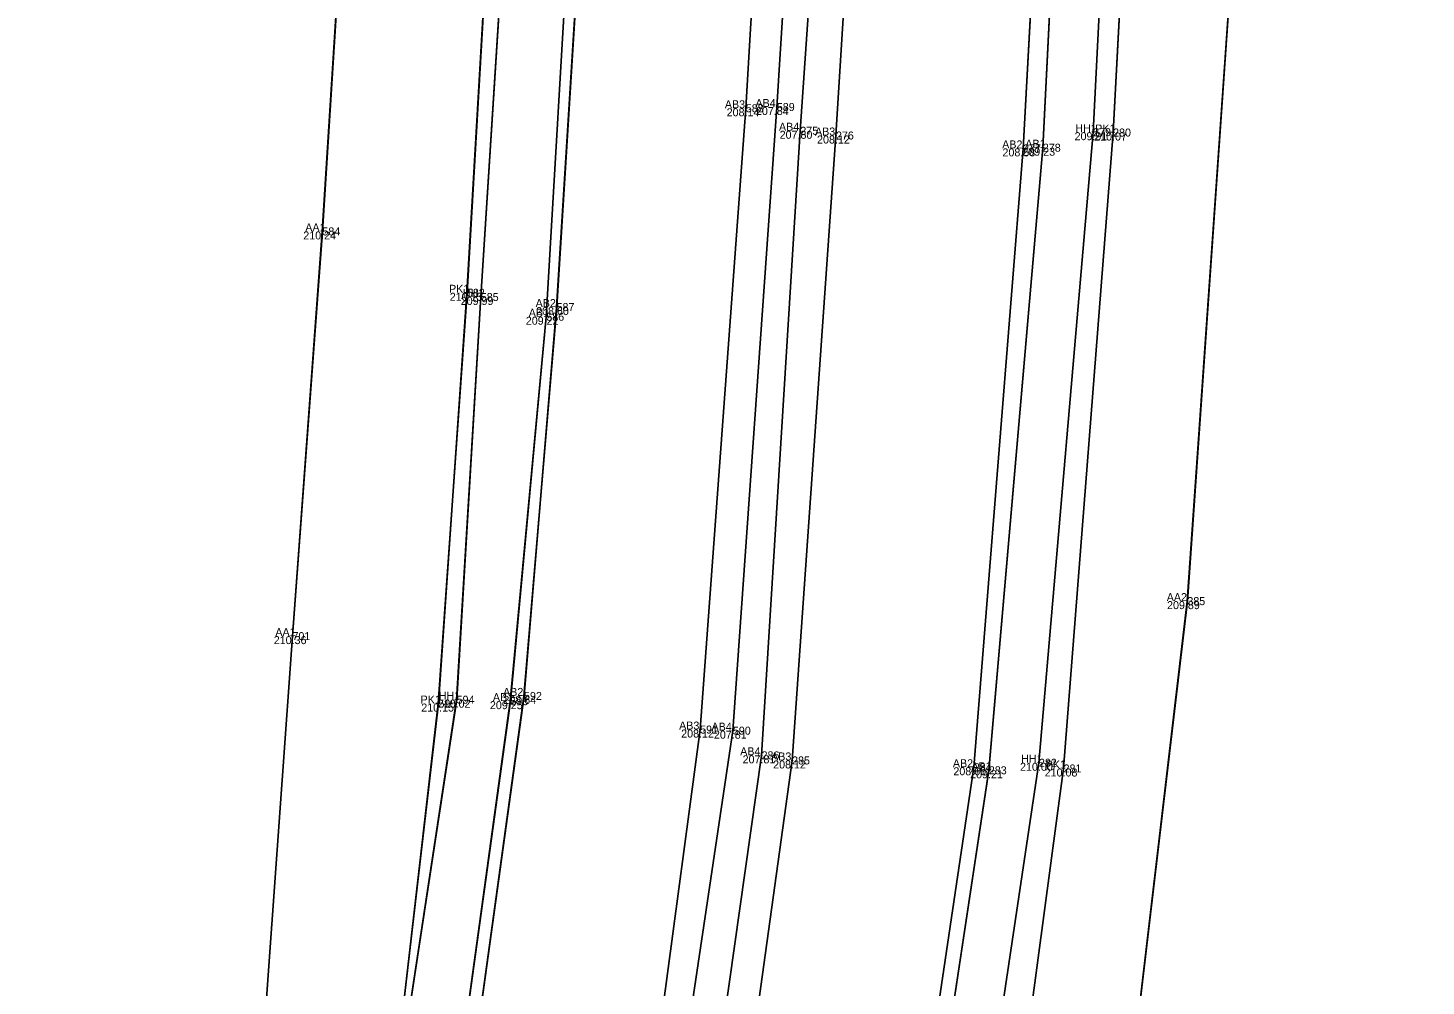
# Model space of a CAD drawing. Extents: x -263091 to -262565, y -1238731 to -1237092.
# Drawn here: x -262851.71 to -262816.76, y -1238047.41 to -1238023.45 of the extents above; entities that cross this region are included whole.
import ezdxf

# ---------------------------------------------------------------- set-up
doc = ezdxf.new("R2010")
doc.units = 0
for name, color, linetype in [('01_Hrana_betónu', 7, 'Continuous'), ('02_Oplotenie', 7, 'Continuous'), ('03_Asfalt', 7, 'Continuous'), ('05_Hrana_terénu', 7, 'Continuous'), ('09_Múrik', 7, 'Continuous'), ('Groma (21)', 7, 'Continuous'), ('Groma (22)', 7, 'Continuous'), ('Groma (23)', 7, 'Continuous'), ('Groma (24)', 7, 'Continuous'), ('U003_Asfalt', 7, 'Continuous'), ('U003_Betónové_múriky', 7, 'Continuous'), ('U003_Betónové_panely', 7, 'Continuous'), ('U003_Zeleň_mimo', 7, 'Continuous'), ('U003_Zeleň_vnútro', 7, 'Continuous'), ('U003_Zeleň_zatrávňovač', 7, 'Continuous'), ('U005_Betóny_prídavné', 7, 'Continuous')]:
    doc.layers.add(name, color=color, linetype=linetype)

msp = doc.modelspace()

# ---------------------------------------------------------------- linework, layer by layer
at = {"layer": '01_Hrana_betónu'}
for points in [[(-262903.088, -1238238.797), (-262890.817, -1238204.479), (-262885.468, -1238189.492), (-262878.003, -1238168.56), (-262870.455, -1238147.513), (-262864.947, -1238132.168), (-262859.037, -1238116.651), (-262848.977, -1238095.826), (-262842.353, -1238078.361), (-262839.446, -1238067.823), (-262836.783, -1238055.069), (-262834.905, -1238040.999), (-262833.763, -1238025.462), (-262832.297, -1238000.555), (-262831.13, -1237981.111), (-262829.791, -1237958.391), (-262828.651, -1237937.03), (-262828.571, -1237935.876)], [(-262827.762, -1237935.927), (-262827.853, -1237937.062), (-262829.049, -1237958.415), (-262830.305, -1237981.211), (-262831.433, -1238000.629), (-262832.987, -1238025.43), (-262834.086, -1238041.027), (-262836.169, -1238055.023), (-262838.684, -1238068.024), (-262841.681, -1238078.569), (-262848.285, -1238096.308), (-262858.162, -1238116.913), (-262863.876, -1238132.122), (-262869.919, -1238147.692), (-262877.244, -1238168.638), (-262884.69, -1238189.67), (-262901.991, -1238238.762)], [(-262827.034, -1237935.973), (-262827.072, -1237937.036), (-262828.491, -1237960.168), (-262829.643, -1237980.454), (-262830.754, -1238002.123), (-262832.4, -1238026.024), (-262833.369, -1238041.644), (-262835.263, -1238055.011), (-262838.048, -1238068.261), (-262841.826, -1238081.232), (-262846.645, -1238094.136), (-262857.777, -1238117.273), (-262863.292, -1238131.948), (-262884.082, -1238190.299), (-262901.352, -1238238.742)], [(-262900.376, -1238238.711), (-262890.192, -1238209.46), (-262883.463, -1238190.564), (-262868.512, -1238148.877), (-262862.514, -1238132.276), (-262857.014, -1238117.706), (-262845.846, -1238094.561), (-262841.058, -1238081.49), (-262837.218, -1238068.474), (-262834.492, -1238055.416), (-262832.606, -1238041.772), (-262831.509, -1238026.143), (-262830.024, -1238002.24), (-262828.826, -1237980.518), (-262827.576, -1237960.277), (-262826.117, -1237937.218), (-262826.079, -1237936.033)]]:
    msp.add_lwpolyline(points, dxfattribs=at)
at = {"layer": '02_Oplotenie'}
for points in [[(-262912.451, -1238238.295), (-262908.254, -1238226.663), (-262901.526, -1238207.942), (-262898.552, -1238199.602), (-262894.22, -1238186.327), (-262886.794, -1238165.648), (-262879.297, -1238144.201), (-262873.976, -1238128.814), (-262867.141, -1238113.572), (-262855.316, -1238089.931), (-262850.675, -1238078.807), (-262846.261, -1238065.654), (-262843.56, -1238054.226), (-262842.344, -1238048.099), (-262841.445, -1238040.349), (-262840.733, -1238030.077), (-262839.013, -1238000.384), (-262838.353, -1237989.712), (-262835.178, -1237935.879)], [(-262819.762, -1237938.034), (-262820.788, -1237960.675), (-262821.837, -1237980.919), (-262823.308, -1238002.106), (-262824.582, -1238026.068), (-262825.82, -1238041.973), (-262827.772, -1238056.552), (-262830.57, -1238069.546), (-262834.589, -1238083.855), (-262839.328, -1238095.835), (-262848.782, -1238120.942), (-262853.684, -1238135.175), (-262859.896, -1238152.781), (-262867.698, -1238174.329), (-262874.833, -1238193.487), (-262881.88, -1238212.036), (-262887.174, -1238225.693), (-262888.829, -1238230.138)]]:
    msp.add_lwpolyline(points, dxfattribs=at)
at = {"layer": '03_Asfalt'}
for points in [[(-262912.678, -1238239.103), (-262913.356, -1238239.285), (-262915.717, -1238239.279), (-262916.328, -1238238.784), (-262916.575, -1238236.319), (-262915.768, -1238233.661), (-262912.404, -1238225.097), (-262904.805, -1238205.606), (-262896.687, -1238184.948), (-262888.478, -1238163.929), (-262880.124, -1238142.63), (-262874.65, -1238128.675), (-262868.549, -1238113.075), (-262858.861, -1238088.481), (-262853.132, -1238074.038), (-262850.084, -1238066.288), (-262845.869, -1238049.471), (-262845.094, -1238038.662), (-262844.346, -1238028.542), (-262842.599, -1238000.955), (-262841.603, -1237985.168), (-262838.824, -1237943.888), (-262838.24, -1237934.633), (-262838.283, -1237933.488)], [(-262816.76, -1237934.791), (-262817.067, -1237940.584), (-262818.198, -1237960.603), (-262819.351, -1237980.318), (-262820.259, -1237997.242), (-262821.106, -1238014.516), (-262822.726, -1238037.787), (-262824.929, -1238056.475), (-262826.695, -1238065.295), (-262832.135, -1238081.046), (-262834.142, -1238085.994), (-262836.111, -1238090.171)]]:
    msp.add_lwpolyline(points, dxfattribs=at)
at = {"layer": '05_Hrana_terénu'}
for points in [[(-262835.062, -1237935.275), (-262834.86, -1237936.333), (-262838.087, -1237989.633), (-262838.484, -1238000.332), (-262840.387, -1238030.181), (-262840.991, -1238040.253), (-262843.126, -1238054.282), (-262845.675, -1238066.436), (-262850.413, -1238079.623), (-262854.798, -1238090.209), (-262863.856, -1238108.78), (-262866.643, -1238114.502), (-262872.333, -1238129.41), (-262877.981, -1238144.625), (-262885.616, -1238166.033), (-262893.121, -1238186.676), (-262898.244, -1238201.149), (-262900.554, -1238208.001), (-262907.375, -1238226.781), (-262911.85, -1238238.364), (-262912.678, -1238239.103)], [(-262849.564, -1238120.544), (-262839.894, -1238095.583), (-262835.301, -1238083.403), (-262831.402, -1238069.334), (-262828.632, -1238056.516), (-262826.436, -1238041.83), (-262825.08, -1238026.06), (-262823.863, -1238001.967), (-262822.633, -1237980.847), (-262821.298, -1237960.54), (-262820.334, -1237939.047), (-262819.871, -1237937.657)]]:
    msp.add_lwpolyline(points, dxfattribs=at)
at = {"layer": '09_Múrik'}
for points in [[(-262845.277, -1238070.627), (-262844.218, -1238066.744), (-262841.577, -1238054.272), (-262839.647, -1238040.289), (-262838.75, -1238030.675), (-262836.979, -1238000.411), (-262836.237, -1237989.843), (-262834.391, -1237956.949), (-262833.055, -1237935.594)], [(-262844.833, -1238070.767), (-262843.906, -1238066.814), (-262841.249, -1238054.245), (-262839.306, -1238040.158), (-262838.493, -1238030.433), (-262836.614, -1238000.277), (-262836.049, -1237989.856), (-262833.996, -1237956.678), (-262832.67, -1237935.618)], [(-262840.924, -1238094.827), (-262836.941, -1238083.068), (-262832.969, -1238069.042), (-262830.214, -1238056.416), (-262828.063, -1238041.942), (-262826.83, -1238026.465), (-262825.494, -1238001.855), (-262824.316, -1237980.84), (-262823.031, -1237960.337), (-262821.719, -1237936.336)], [(-262840.6, -1238094.732), (-262836.43, -1238082.967), (-262832.633, -1238069.1), (-262829.86, -1238056.421), (-262827.688, -1238042.018), (-262826.338, -1238026.448), (-262825.108, -1238001.872), (-262823.89, -1237980.741), (-262822.602, -1237960.47), (-262821.253, -1237936.39)]]:
    msp.add_lwpolyline(points, dxfattribs=at)
at = {"layer": 'Groma (21)'}
for centre in [(-262833.763, -1238025.462), (-262832.987, -1238025.43), (-262832.4, -1238026.024), (-262831.509, -1238026.143), (-262825.08, -1238026.06), (-262824.582, -1238026.068), (-262826.83, -1238026.465), (-262826.338, -1238026.448), (-262844.346, -1238028.542), (-262840.733, -1238030.077), (-262840.387, -1238030.181), (-262838.493, -1238030.433), (-262838.75, -1238030.675), (-262822.726, -1238037.787), (-262845.094, -1238038.662), (-262839.306, -1238040.158), (-262841.445, -1238040.349), (-262840.991, -1238040.253), (-262839.647, -1238040.289), (-262834.905, -1238040.999), (-262834.086, -1238041.027), (-262833.369, -1238041.644), (-262832.606, -1238041.772), (-262828.063, -1238041.942), (-262826.436, -1238041.83), (-262827.688, -1238042.018), (-262825.82, -1238041.973)]:
    msp.add_circle(centre, 0.01, dxfattribs=at)
at = {"layer": 'U003_Asfalt'}
for points in [[(-262836.86, -1238089.78), (-262834.59, -1238083.86), (-262830.57, -1238069.55), (-262827.77, -1238056.55), (-262825.82, -1238041.97), (-262824.58, -1238026.07), (-262823.31, -1238002.11), (-262821.84, -1237980.92), (-262820.79, -1237960.68), (-262819.76, -1237938.03), (-262819.87, -1237937.66), (-262818.51, -1237937.77), (-262818.3, -1237934.7)], [(-262816.76, -1237934.79), (-262817.07, -1237940.58), (-262818.2, -1237960.6), (-262819.35, -1237980.32), (-262820.26, -1237997.24), (-262821.11, -1238014.52), (-262822.73, -1238037.79), (-262824.93, -1238056.48), (-262826.7, -1238065.3), (-262832.14, -1238081.05), (-262834.14, -1238085.99), (-262836.11, -1238090.17), (-262836.86, -1238089.78)], [(-262821.11, -1238014.52), (-262822.73, -1238037.79), (-262824.93, -1238056.48), (-262826.7, -1238065.3), (-262832.14, -1238081.05), (-262834.14, -1238085.99), (-262836.11, -1238090.17), (-262836.86, -1238089.78), (-262834.59, -1238083.86), (-262830.57, -1238069.55), (-262827.77, -1238056.55), (-262825.82, -1238041.97), (-262824.58, -1238026.07), (-262823.31, -1238002.11)]]:
    msp.add_lwpolyline(points, dxfattribs=at)
at = {"layer": 'U003_Betónové_múriky'}
for points in [[(-262834.39, -1237956.95), (-262833.05, -1237935.59), (-262832.67, -1237935.62), (-262834, -1237956.68), (-262836.05, -1237989.86), (-262836.61, -1238000.28), (-262838.49, -1238030.43), (-262839.31, -1238040.16), (-262841.25, -1238054.25), (-262843.91, -1238066.81), (-262844.83, -1238070.77), (-262845.28, -1238070.63), (-262844.22, -1238066.74), (-262841.58, -1238054.27), (-262839.65, -1238040.29), (-262838.75, -1238030.68), (-262836.98, -1238000.41), (-262836.24, -1237989.84)], [(-262821.25, -1237936.39), (-262822.6, -1237960.47), (-262823.89, -1237980.74), (-262825.11, -1238001.87), (-262826.34, -1238026.45), (-262827.69, -1238042.02), (-262829.86, -1238056.42), (-262832.63, -1238069.1), (-262836.43, -1238082.97), (-262840.6, -1238094.73), (-262840.92, -1238094.83), (-262836.94, -1238083.07), (-262832.97, -1238069.04), (-262830.21, -1238056.42), (-262828.06, -1238041.94), (-262826.83, -1238026.47), (-262825.49, -1238001.86), (-262824.32, -1237980.84), (-262823.03, -1237960.34), (-262821.72, -1237936.34)]]:
    msp.add_lwpolyline(points, close=True, dxfattribs=at)
for points in [[(-262836.24, -1237989.84), (-262834.39, -1237956.95), (-262833.05, -1237935.59), (-262832.67, -1237935.62), (-262834, -1237956.68), (-262836.05, -1237989.86), (-262836.61, -1238000.28), (-262838.49, -1238030.43), (-262839.31, -1238040.16), (-262841.25, -1238054.25), (-262843.91, -1238066.81), (-262844.83, -1238070.77), (-262845.28, -1238070.63), (-262844.22, -1238066.74), (-262841.58, -1238054.27), (-262839.65, -1238040.29), (-262838.75, -1238030.68), (-262836.98, -1238000.41), (-262836.24, -1237989.84)], [(-262821.72, -1237936.34), (-262821.25, -1237936.39), (-262822.6, -1237960.47), (-262823.89, -1237980.74), (-262825.11, -1238001.87), (-262826.34, -1238026.45), (-262827.69, -1238042.02), (-262829.86, -1238056.42), (-262832.63, -1238069.1), (-262836.43, -1238082.97), (-262840.6, -1238094.73), (-262840.92, -1238094.83), (-262836.94, -1238083.07), (-262832.97, -1238069.04), (-262830.21, -1238056.42), (-262828.06, -1238041.94), (-262826.83, -1238026.47), (-262825.49, -1238001.86), (-262824.32, -1237980.84), (-262823.03, -1237960.34), (-262821.72, -1237936.34)]]:
    msp.add_lwpolyline(points, dxfattribs=at)
at = {"layer": 'U003_Betónové_panely'}
for points in [[(-262863.7, -1238113.97), (-262862.86, -1238112.21), (-262862.02, -1238109.74), (-262852.53, -1238091.41), (-262847.76, -1238078.52), (-262845.51, -1238070.71), (-262845.28, -1238070.63), (-262844.83, -1238070.77), (-262843.91, -1238066.81), (-262841.25, -1238054.25), (-262839.31, -1238040.16), (-262838.49, -1238030.43), (-262836.61, -1238000.28), (-262836.05, -1237989.86), (-262834, -1237956.68), (-262832.67, -1237935.62), (-262832.64, -1237935.62), (-262832.51, -1237933.84)], [(-262863.7, -1238113.97), (-262862.86, -1238112.21), (-262862.02, -1238109.74), (-262852.53, -1238091.41), (-262847.76, -1238078.52), (-262845.51, -1238070.71), (-262845.28, -1238070.63), (-262844.83, -1238070.77), (-262843.91, -1238066.81), (-262841.25, -1238054.25), (-262839.31, -1238040.16), (-262838.49, -1238030.43), (-262836.61, -1238000.28), (-262836.05, -1237989.86), (-262834, -1237956.68), (-262832.67, -1237935.62), (-262832.64, -1237935.62), (-262832.51, -1237933.84)], [(-262822, -1237934.47), (-262822.23, -1237936.28), (-262821.72, -1237936.34), (-262823.03, -1237960.34), (-262824.32, -1237980.84), (-262825.49, -1238001.86), (-262826.83, -1238026.47), (-262828.06, -1238041.94), (-262830.21, -1238056.42), (-262832.97, -1238069.04), (-262836.94, -1238083.07), (-262840.92, -1238094.83), (-262840.6, -1238094.73), (-262841.76, -1238095.81), (-262851.46, -1238119.84), (-262857.2, -1238134.12), (-262863.32, -1238150.73), (-262871.41, -1238173.11), (-262878.16, -1238192.14), (-262884.61, -1238210.94), (-262889.86, -1238225.24), (-262892.75, -1238232.5), (-262895.19, -1238238.55), (-262900.83, -1238252.4)], [(-262822, -1237934.47), (-262822.23, -1237936.28), (-262821.72, -1237936.34), (-262823.03, -1237960.34), (-262824.32, -1237980.84), (-262825.49, -1238001.86), (-262826.83, -1238026.47), (-262828.06, -1238041.94), (-262830.21, -1238056.42), (-262832.97, -1238069.04), (-262836.94, -1238083.07), (-262840.92, -1238094.83), (-262840.6, -1238094.73), (-262841.76, -1238095.81), (-262851.46, -1238119.84), (-262857.2, -1238134.12), (-262863.32, -1238150.73), (-262871.41, -1238173.11), (-262878.16, -1238192.14), (-262884.61, -1238210.94), (-262889.86, -1238225.24), (-262892.75, -1238232.5), (-262895.19, -1238238.55), (-262900.83, -1238252.4)]]:
    msp.add_lwpolyline(points, dxfattribs=at)
at = {"layer": 'U003_Zeleň_mimo'}
for points in [[(-262868.55, -1238113.08), (-262858.86, -1238088.48), (-262853.13, -1238074.04), (-262850.08, -1238066.29), (-262845.87, -1238049.47), (-262845.09, -1238038.66), (-262844.35, -1238028.54), (-262842.6, -1238000.96), (-262841.6, -1237985.17), (-262838.82, -1237943.89), (-262838.24, -1237934.63)], [(-262836.32, -1237934.59), (-262836.29, -1237935.17), (-262835.06, -1237935.28), (-262835.18, -1237935.88), (-262838.35, -1237989.71), (-262839.01, -1238000.38), (-262840.73, -1238030.08), (-262841.45, -1238040.35), (-262842.34, -1238048.1), (-262843.56, -1238054.23), (-262846.26, -1238065.65), (-262850.68, -1238078.81), (-262855.32, -1238089.93), (-262867.14, -1238113.57)]]:
    msp.add_lwpolyline(points, dxfattribs=at)
at = {"layer": 'U003_Zeleň_vnútro'}
for points in [[(-262849.56, -1238120.54), (-262839.89, -1238095.58), (-262835.3, -1238083.4), (-262831.4, -1238069.33), (-262828.63, -1238056.52), (-262826.44, -1238041.83), (-262825.08, -1238026.06), (-262823.86, -1238001.97), (-262822.63, -1237980.85), (-262821.3, -1237960.54), (-262820.33, -1237939.05), (-262819.87, -1237937.66), (-262819.76, -1237938.03), (-262820.79, -1237960.68), (-262821.84, -1237980.92), (-262823.31, -1238002.11), (-262824.58, -1238026.07), (-262825.82, -1238041.97), (-262827.77, -1238056.55), (-262830.57, -1238069.55), (-262834.59, -1238083.86), (-262839.33, -1238095.84), (-262848.78, -1238120.94)], [(-262849.56, -1238120.54), (-262839.89, -1238095.58), (-262835.3, -1238083.4), (-262831.4, -1238069.33), (-262828.63, -1238056.52), (-262826.44, -1238041.83), (-262825.08, -1238026.06), (-262823.86, -1238001.97), (-262822.63, -1237980.85), (-262821.3, -1237960.54), (-262820.33, -1237939.05), (-262819.87, -1237937.66), (-262819.76, -1237938.03), (-262820.79, -1237960.68), (-262821.84, -1237980.92), (-262823.31, -1238002.11), (-262824.58, -1238026.07), (-262825.82, -1238041.97), (-262827.77, -1238056.55), (-262830.57, -1238069.55), (-262834.59, -1238083.86), (-262839.33, -1238095.84), (-262848.78, -1238120.94)], [(-262838.48, -1238000.33), (-262840.39, -1238030.18), (-262840.99, -1238040.25), (-262843.13, -1238054.28), (-262845.68, -1238066.44), (-262850.41, -1238079.62), (-262854.8, -1238090.21), (-262863.86, -1238108.78), (-262863.4, -1238109.07), (-262864.42, -1238111.37), (-262865.55, -1238113.22)], [(-262838.48, -1238000.33), (-262840.39, -1238030.18), (-262840.99, -1238040.25), (-262843.13, -1238054.28), (-262845.68, -1238066.44), (-262850.41, -1238079.62), (-262854.8, -1238090.21), (-262863.86, -1238108.78), (-262863.4, -1238109.07), (-262864.42, -1238111.37), (-262865.55, -1238113.22)], [(-262867.14, -1238113.57), (-262855.32, -1238089.93), (-262850.68, -1238078.81), (-262846.26, -1238065.65), (-262843.56, -1238054.23), (-262842.34, -1238048.1), (-262841.45, -1238040.35), (-262840.73, -1238030.08), (-262839.01, -1238000.38)], [(-262867.14, -1238113.57), (-262855.32, -1238089.93), (-262850.68, -1238078.81), (-262846.26, -1238065.65), (-262843.56, -1238054.23), (-262842.34, -1238048.1), (-262841.45, -1238040.35), (-262840.73, -1238030.08), (-262839.01, -1238000.38)]]:
    msp.add_lwpolyline(points, dxfattribs=at)
at = {"layer": 'U003_Zeleň_zatrávňovač'}
for points in [[(-262836.98, -1238000.41), (-262838.75, -1238030.68), (-262839.65, -1238040.29), (-262841.58, -1238054.27), (-262844.22, -1238066.74), (-262845.28, -1238070.63), (-262845.51, -1238070.71), (-262847.76, -1238078.52), (-262852.53, -1238091.41), (-262862.02, -1238109.74), (-262863.4, -1238109.07), (-262863.86, -1238108.78), (-262854.8, -1238090.21), (-262850.41, -1238079.62), (-262845.68, -1238066.44), (-262843.13, -1238054.28), (-262840.99, -1238040.25), (-262840.39, -1238030.18), (-262838.48, -1238000.33)], [(-262862.02, -1238109.74), (-262863.4, -1238109.07), (-262863.86, -1238108.78), (-262854.8, -1238090.21), (-262850.41, -1238079.62), (-262845.68, -1238066.44), (-262843.13, -1238054.28), (-262840.99, -1238040.25), (-262840.39, -1238030.18), (-262838.48, -1238000.33)], [(-262836.98, -1238000.41), (-262838.75, -1238030.68), (-262839.65, -1238040.29), (-262841.58, -1238054.27), (-262844.22, -1238066.74), (-262845.28, -1238070.63), (-262845.51, -1238070.71), (-262847.76, -1238078.52), (-262852.53, -1238091.41), (-262862.02, -1238109.74)], [(-262851.46, -1238119.84), (-262841.76, -1238095.81), (-262840.6, -1238094.73), (-262836.43, -1238082.97), (-262832.63, -1238069.1), (-262829.86, -1238056.42), (-262827.69, -1238042.02), (-262826.34, -1238026.45), (-262825.11, -1238001.87)], [(-262823.86, -1238001.97), (-262825.08, -1238026.06), (-262826.44, -1238041.83), (-262828.63, -1238056.52), (-262831.4, -1238069.33), (-262835.3, -1238083.4), (-262839.89, -1238095.58), (-262849.56, -1238120.54)]]:
    msp.add_lwpolyline(points, dxfattribs=at)
at = {"layer": 'U005_Betóny_prídavné'}
for points in [[(-262851.46, -1238119.84), (-262841.76, -1238095.81), (-262840.6, -1238094.73), (-262836.43, -1238082.97), (-262832.63, -1238069.1), (-262829.86, -1238056.42), (-262827.69, -1238042.02), (-262826.34, -1238026.45), (-262825.11, -1238001.87)], [(-262823.86, -1238001.97), (-262825.08, -1238026.06), (-262826.44, -1238041.83), (-262828.63, -1238056.52), (-262831.4, -1238069.33), (-262835.3, -1238083.4), (-262839.89, -1238095.58), (-262849.56, -1238120.54)]]:
    msp.add_lwpolyline(points, dxfattribs=at)

# ---------------------------------------------------------------- texts
at = {"layer": 'Groma (22)'}
for s, p in [('588', (-262833.763, -1238025.562)), ('589', (-262832.987, -1238025.53)), ('275', (-262832.4, -1238026.124)), ('276', (-262831.509, -1238026.243)), ('279', (-262825.08, -1238026.16)), ('280', (-262824.582, -1238026.168)), ('277', (-262826.83, -1238026.565)), ('278', (-262826.338, -1238026.548)), ('584', (-262844.346, -1238028.642)), ('582', (-262840.733, -1238030.177)), ('585', (-262840.387, -1238030.281)), ('587', (-262838.493, -1238030.533)), ('586', (-262838.75, -1238030.775)), ('385', (-262822.726, -1238037.887)), ('701', (-262845.094, -1238038.762)), ('594', (-262840.991, -1238040.353)), ('593', (-262839.647, -1238040.389)), ('592', (-262839.306, -1238040.258)), ('595', (-262841.445, -1238040.449)), ('591', (-262834.905, -1238041.099)), ('590', (-262834.086, -1238041.127)), ('286', (-262833.369, -1238041.744)), ('285', (-262832.606, -1238041.872)), ('284', (-262828.063, -1238042.042)), ('283', (-262827.688, -1238042.118)), ('282', (-262826.436, -1238041.93)), ('281', (-262825.82, -1238042.073))]:
    msp.add_text(s, height=0.2, dxfattribs=at).set_placement(p)
at = {"layer": 'Groma (23)'}
for s, p in [('208.14', (-262834.241, -1238025.662)), ('207.84', (-262833.509, -1238025.63)), ('207.80', (-262832.917, -1238026.224)), ('208.12', (-262831.982, -1238026.343)), ('209.91', (-262825.544, -1238026.26)), ('210.07', (-262825.055, -1238026.268)), ('208.58', (-262827.347, -1238026.665)), ('209.23', (-262826.85, -1238026.648)), ('210.24', (-262844.824, -1238028.742)), ('210.15', (-262841.163, -1238030.277)), ('209.99', (-262840.889, -1238030.381)), ('208.60', (-262839.004, -1238030.633)), ('209.22', (-262839.262, -1238030.875)), ('209.89', (-262823.233, -1238037.987)), ('210.36', (-262845.562, -1238038.862)), ('208.64', (-262839.823, -1238040.358)), ('210.15', (-262841.875, -1238040.549)), ('210.02', (-262841.463, -1238040.453)), ('209.25', (-262840.159, -1238040.489)), ('208.12', (-262835.378, -1238041.199)), ('207.81', (-262834.56, -1238041.227)), ('207.81', (-262833.843, -1238041.844)), ('208.12', (-262833.079, -1238041.972)), ('208.60', (-262828.574, -1238042.142)), ('210.00', (-262826.908, -1238042.03)), ('209.21', (-262828.156, -1238042.218)), ('210.08', (-262826.292, -1238042.173))]:
    msp.add_text(s, height=0.2, dxfattribs=at).set_placement(p)
at = {"layer": 'Groma (24)'}
for s, p in [('AB3', (-262834.287, -1238025.462)), ('AB4', (-262833.521, -1238025.43)), ('AB4', (-262832.934, -1238026.024)), ('HH1', (-262825.527, -1238026.06)), ('PK1', (-262825.029, -1238026.068)), ('AB3', (-262832.033, -1238026.143)), ('AB2', (-262827.354, -1238026.465)), ('AB1', (-262826.776, -1238026.448)), ('AA1', (-262844.774, -1238028.542)), ('PK1', (-262841.18, -1238030.077)), ('HH1', (-262840.834, -1238030.181)), ('AB2', (-262839.017, -1238030.433)), ('AB1', (-262839.188, -1238030.675)), ('AA2', (-262823.241, -1238037.787)), ('AA1', (-262845.522, -1238038.662)), ('PK1', (-262841.892, -1238040.349)), ('HH1', (-262841.438, -1238040.253)), ('AB1', (-262840.085, -1238040.289)), ('AB2', (-262839.83, -1238040.158)), ('AB3', (-262835.429, -1238040.999)), ('AB4', (-262834.62, -1238041.027)), ('AB4', (-262833.903, -1238041.644)), ('AB3', (-262833.13, -1238041.772)), ('AB2', (-262828.587, -1238041.942)), ('AB1', (-262828.126, -1238042.018)), ('HH1', (-262826.883, -1238041.83)), ('PK1', (-262826.267, -1238041.973))]:
    msp.add_text(s, height=0.2, dxfattribs=at).set_placement(p)

doc.saveas('drawing.dxf')
